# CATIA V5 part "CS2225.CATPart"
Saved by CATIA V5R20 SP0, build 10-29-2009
Part number: CS2225
Revision: 6
Definition: design
Nomenclature: CS2225
Source: made
Description: NOT SPECIFIED
Bounding box of the stored display mesh (mm): x -23.825 to 24, y -24 to 24, z -45 to 12
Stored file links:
  C:\Users\Raffaele\Desktop\3D X SITO CF\BOLEX\20-TILTED COLUMN SUPPORT\CS2225.CATPart
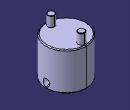
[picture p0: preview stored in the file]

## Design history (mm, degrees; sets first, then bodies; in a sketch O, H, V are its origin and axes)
Body1 "MANIFOLD_SOLID_BREP #711" (main body)
  Solid1: solid without history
